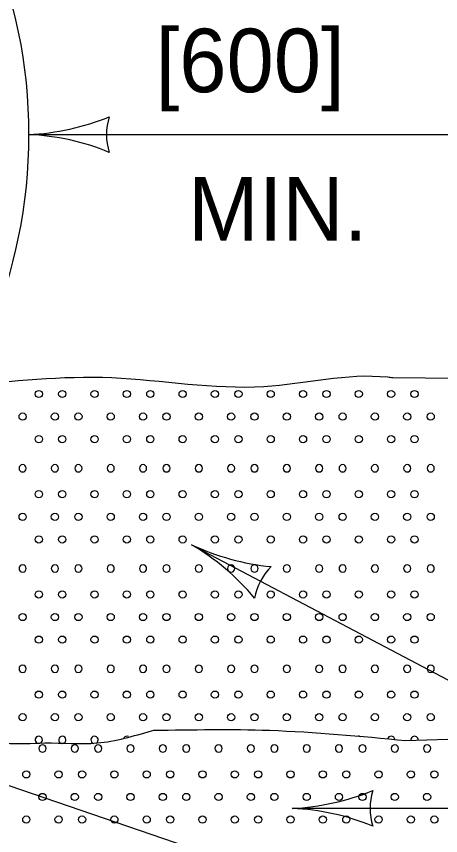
# Model space of a CAD drawing. Extents: x 49991.4 to 50021, y 49987.6 to 50011.4.
# Drawn here: x 50003.823 to 50004.224, y 49993.056 to 49993.83 of the extents above; entities that cross this region are included whole.
import ezdxf

# ---------------------------------------------------------------- set-up
doc = ezdxf.new("R2010")
doc.units = 0
for name, color, linetype in [('Level 1', 7, 'Continuous'), ('Level 2', 7, 'Continuous'), ('Level 3', 7, 'Continuous')]:
    doc.layers.add(name, color=color, linetype=linetype)

msp = doc.modelspace()

# ---------------------------------------------------------------- linework, layer by layer
at = {"layer": 'Level 1'}
msp.add_line((50003.95088, 49993.15536), (50003.95299, 49993.15586), dxfattribs=at)
for points in [[(50004.17861, 49993.48883), (50004.23958, 49993.4884), (50004.31501, 49993.48051), (50004.32066, 49993.47642)], [(50004.19101, 49993.14623), (50004.25047, 49993.14814), (50004.31739, 49993.14216)]]:
    msp.add_lwpolyline(points, dxfattribs=at)
for centre, radius in [((50003.35501, 49993.71818), 0.48), ((50003.84458, 49993.47333), 0.00341), ((50003.86672, 49993.47333), 0.00341), ((50003.8972, 49993.47333), 0.00341), ((50003.92768, 49993.47333), 0.00341), ((50003.94982, 49993.47333), 0.00341), ((50003.9803, 49993.47333), 0.00341), ((50004.01078, 49993.47333), 0.00341), ((50004.03292, 49993.47333), 0.00341), ((50004.0634, 49993.47333), 0.00341), ((50004.09388, 49993.47333), 0.00341), ((50004.11602, 49993.47333), 0.00341), ((50004.1465, 49993.47333), 0.00341), ((50004.17698, 49993.47333), 0.00341), ((50004.19912, 49993.47333), 0.00341), ((50003.82934, 49993.452), 0.00341), ((50003.82934, 49993.452), 0.00341), ((50003.85982, 49993.452), 0.00341), ((50003.88196, 49993.452), 0.00341), ((50003.91244, 49993.452), 0.00341), ((50003.91244, 49993.452), 0.00341), ((50003.94292, 49993.452), 0.00341), ((50003.96506, 49993.452), 0.00341), ((50003.99554, 49993.452), 0.00341), ((50003.99554, 49993.452), 0.00341), ((50004.02602, 49993.452), 0.00341), ((50004.04816, 49993.452), 0.00341), ((50004.07864, 49993.452), 0.00341), ((50004.07864, 49993.452), 0.00341), ((50004.10912, 49993.452), 0.00341), ((50004.13126, 49993.452), 0.00341), ((50004.16174, 49993.452), 0.00341), ((50004.16174, 49993.452), 0.00341), ((50004.19222, 49993.452), 0.00341), ((50004.21436, 49993.452), 0.00341), ((50003.84458, 49993.43066), 0.00341), ((50003.86672, 49993.43066), 0.00341), ((50003.8972, 49993.43066), 0.00341), ((50003.92768, 49993.43066), 0.00341), ((50003.94982, 49993.43066), 0.00341), ((50003.9803, 49993.43066), 0.00341), ((50004.01078, 49993.43066), 0.00341), ((50004.03292, 49993.43066), 0.00341), ((50004.0634, 49993.43066), 0.00341), ((50004.09388, 49993.43066), 0.00341), ((50004.11602, 49993.43066), 0.00341), ((50004.1465, 49993.43066), 0.00341), ((50004.17698, 49993.43066), 0.00341), ((50004.19912, 49993.43066), 0.00341), ((50003.84458, 49993.37873), 0.00341), ((50003.86672, 49993.37873), 0.00341), ((50003.8972, 49993.37873), 0.00341), ((50003.92768, 49993.37873), 0.00341), ((50003.94982, 49993.37873), 0.00341), ((50003.9803, 49993.37873), 0.00341), ((50004.01078, 49993.37873), 0.00341), ((50004.03292, 49993.37873), 0.00341), ((50004.0634, 49993.37873), 0.00341), ((50004.09388, 49993.37873), 0.00341), ((50004.11602, 49993.37873), 0.00341), ((50004.1465, 49993.37873), 0.00341), ((50004.17698, 49993.37873), 0.00341), ((50004.19912, 49993.37873), 0.00341), ((50003.82934, 49993.3574), 0.00341), ((50003.82934, 49993.3574), 0.00341), ((50003.85982, 49993.3574), 0.00341), ((50003.88196, 49993.3574), 0.00341), ((50003.91244, 49993.3574), 0.00341), ((50003.91244, 49993.3574), 0.00341), ((50003.94292, 49993.3574), 0.00341), ((50003.96506, 49993.3574), 0.00341), ((50003.99554, 49993.3574), 0.00341), ((50003.99554, 49993.3574), 0.00341), ((50004.02602, 49993.3574), 0.00341), ((50004.04816, 49993.3574), 0.00341), ((50004.07864, 49993.3574), 0.00341), ((50004.07864, 49993.3574), 0.00341), ((50004.10912, 49993.3574), 0.00341), ((50004.13126, 49993.3574), 0.00341), ((50004.16174, 49993.3574), 0.00341), ((50004.16174, 49993.3574), 0.00341), ((50004.19222, 49993.3574), 0.00341), ((50004.21436, 49993.3574), 0.00341), ((50003.84458, 49993.33606), 0.00341), ((50003.86672, 49993.33606), 0.00341), ((50003.8972, 49993.33606), 0.00341), ((50003.92768, 49993.33606), 0.00341), ((50003.94982, 49993.33606), 0.00341), ((50003.9803, 49993.33606), 0.00341), ((50004.01078, 49993.33606), 0.00341), ((50004.03292, 49993.33606), 0.00341), ((50004.0634, 49993.33606), 0.00341), ((50004.09388, 49993.33606), 0.00341), ((50004.11602, 49993.33606), 0.00341), ((50004.1465, 49993.33606), 0.00341), ((50004.17698, 49993.33606), 0.00341), ((50004.19912, 49993.33606), 0.00341), ((50003.84458, 49993.28413), 0.00341), ((50003.86672, 49993.28413), 0.00341), ((50003.8972, 49993.28413), 0.00341), ((50003.92768, 49993.28413), 0.00341), ((50003.94982, 49993.28413), 0.00341), ((50003.9803, 49993.28413), 0.00341), ((50004.01078, 49993.28413), 0.00341), ((50004.03292, 49993.28413), 0.00341), ((50004.0634, 49993.28413), 0.00341), ((50004.09388, 49993.28413), 0.00341), ((50004.11602, 49993.28413), 0.00341), ((50004.1465, 49993.28413), 0.00341), ((50004.17698, 49993.28413), 0.00341), ((50004.19912, 49993.28413), 0.00341), ((50003.82934, 49993.2628), 0.00341), ((50003.82934, 49993.2628), 0.00341), ((50003.85982, 49993.2628), 0.00341), ((50003.88196, 49993.2628), 0.00341), ((50003.91244, 49993.2628), 0.00341), ((50003.91244, 49993.2628), 0.00341), ((50003.94292, 49993.2628), 0.00341), ((50003.96506, 49993.2628), 0.00341), ((50003.99554, 49993.2628), 0.00341), ((50003.99554, 49993.2628), 0.00341), ((50004.02602, 49993.2628), 0.00341), ((50004.04816, 49993.2628), 0.00341), ((50004.07864, 49993.2628), 0.00341), ((50004.07864, 49993.2628), 0.00341), ((50004.10912, 49993.2628), 0.00341), ((50004.13126, 49993.2628), 0.00341), ((50004.16174, 49993.2628), 0.00341), ((50004.16174, 49993.2628), 0.00341), ((50004.19222, 49993.2628), 0.00341), ((50004.21436, 49993.2628), 0.00341), ((50003.84458, 49993.24146), 0.00341), ((50003.86672, 49993.24146), 0.00341), ((50003.8972, 49993.24146), 0.00341), ((50003.92768, 49993.24146), 0.00341), ((50003.94982, 49993.24146), 0.00341), ((50003.9803, 49993.24146), 0.00341), ((50004.01078, 49993.24146), 0.00341), ((50004.03292, 49993.24146), 0.00341), ((50004.0634, 49993.24146), 0.00341), ((50004.09388, 49993.24146), 0.00341), ((50004.11602, 49993.24146), 0.00341), ((50004.1465, 49993.24146), 0.00341), ((50004.17698, 49993.24146), 0.00341), ((50004.19912, 49993.24146), 0.00341), ((50003.84458, 49993.18953), 0.00341), ((50003.86672, 49993.18953), 0.00341), ((50003.8972, 49993.18953), 0.00341), ((50003.92768, 49993.18953), 0.00341), ((50003.94982, 49993.18953), 0.00341), ((50003.9803, 49993.18953), 0.00341), ((50004.01078, 49993.18953), 0.00341), ((50004.03292, 49993.18953), 0.00341), ((50004.0634, 49993.18953), 0.00341), ((50004.09388, 49993.18953), 0.00341), ((50004.11602, 49993.18953), 0.00341), ((50004.1465, 49993.18953), 0.00341), ((50004.17698, 49993.18953), 0.00341), ((50004.19912, 49993.18953), 0.00341), ((50003.82934, 49993.1682), 0.00341), ((50003.82934, 49993.1682), 0.00341), ((50003.85982, 49993.1682), 0.00341), ((50003.88196, 49993.1682), 0.00341), ((50003.91244, 49993.1682), 0.00341), ((50003.91244, 49993.1682), 0.00341), ((50003.94292, 49993.1682), 0.00341), ((50003.96506, 49993.1682), 0.00341), ((50003.99554, 49993.1682), 0.00341), ((50003.99554, 49993.1682), 0.00341), ((50004.02602, 49993.1682), 0.00341), ((50004.04816, 49993.1682), 0.00341), ((50004.07864, 49993.1682), 0.00341), ((50004.07864, 49993.1682), 0.00341), ((50004.10912, 49993.1682), 0.00341), ((50004.13126, 49993.1682), 0.00341), ((50004.16174, 49993.1682), 0.00341), ((50004.16174, 49993.1682), 0.00341), ((50004.19222, 49993.1682), 0.00341), ((50004.21436, 49993.1682), 0.00341), ((50003.8328, 49993.1143), 0.00341), ((50003.86328, 49993.1143), 0.00341), ((50003.88542, 49993.1143), 0.00341), ((50003.9159, 49993.1143), 0.00341), ((50003.94638, 49993.1143), 0.00341), ((50003.96852, 49993.1143), 0.00341), ((50003.999, 49993.1143), 0.00341), ((50004.02948, 49993.1143), 0.00341), ((50004.05162, 49993.1143), 0.00341), ((50004.0821, 49993.1143), 0.00341), ((50004.11258, 49993.1143), 0.00341), ((50004.13472, 49993.1143), 0.00341), ((50004.1652, 49993.1143), 0.00341), ((50004.19568, 49993.1143), 0.00341), ((50004.21782, 49993.1143), 0.00341), ((50003.84804, 49993.09296), 0.00341), ((50003.84804, 49993.09296), 0.00341), ((50003.87852, 49993.09296), 0.00341), ((50003.90066, 49993.09296), 0.00341), ((50003.93114, 49993.09296), 0.00341), ((50003.93114, 49993.09296), 0.00341), ((50003.96162, 49993.09296), 0.00341), ((50003.98376, 49993.09296), 0.00341), ((50004.01424, 49993.09296), 0.00341), ((50004.01424, 49993.09296), 0.00341), ((50004.04472, 49993.09296), 0.00341), ((50004.06686, 49993.09296), 0.00341), ((50004.09734, 49993.09296), 0.00341), ((50004.09734, 49993.09296), 0.00341), ((50004.12782, 49993.09296), 0.00341), ((50004.14996, 49993.09296), 0.00341), ((50004.18044, 49993.09296), 0.00341), ((50004.18044, 49993.09296), 0.00341), ((50004.21092, 49993.09296), 0.00341), ((50003.8328, 49993.07162), 0.00341), ((50003.86328, 49993.07162), 0.00341), ((50003.88542, 49993.07162), 0.00341), ((50003.9159, 49993.07162), 0.00341), ((50003.94638, 49993.07162), 0.00341), ((50003.96852, 49993.07162), 0.00341), ((50003.999, 49993.07162), 0.00341), ((50004.02948, 49993.07162), 0.00341), ((50004.05162, 49993.07162), 0.00341), ((50004.0821, 49993.07162), 0.00341), ((50004.11258, 49993.07162), 0.00341), ((50004.13472, 49993.07162), 0.00341), ((50004.1652, 49993.07162), 0.00341), ((50004.19568, 49993.07162), 0.00341), ((50004.21782, 49993.07162), 0.00341)]:
    msp.add_circle(centre, radius, dxfattribs=at)
for centre, start, end in [((50003.82934, 49993.40323), 0, 180), ((50003.85982, 49993.40323), 0, 180), ((50003.88196, 49993.40323), 0, 180), ((50003.91244, 49993.40323), 0, 180), ((50003.94292, 49993.40323), 0, 180), ((50003.96506, 49993.40323), 0, 180), ((50003.99554, 49993.40323), 0, 180), ((50004.02602, 49993.40323), 0, 180), ((50004.04816, 49993.40323), 0, 180), ((50004.07864, 49993.40323), 0, 180), ((50004.10912, 49993.40323), 0, 180), ((50004.13126, 49993.40323), 0, 180), ((50004.16174, 49993.40323), 0, 180), ((50004.19222, 49993.40323), 0, 180), ((50004.21436, 49993.40323), 0, 180), ((50003.82934, 49993.40312), 180, 0), ((50003.82934, 49993.40312), 180, 0), ((50003.85982, 49993.40312), 180, 0), ((50003.88196, 49993.40312), 180, 0), ((50003.91244, 49993.40312), 180, 0), ((50003.91244, 49993.40312), 180, 0), ((50003.94292, 49993.40312), 180, 0), ((50003.96506, 49993.40312), 180, 0), ((50003.99554, 49993.40312), 180, 0), ((50003.99554, 49993.40312), 180, 0), ((50004.02602, 49993.40312), 180, 0), ((50004.04816, 49993.40312), 180, 0), ((50004.07864, 49993.40312), 180, 0), ((50004.07864, 49993.40312), 180, 0), ((50004.10912, 49993.40312), 180, 0), ((50004.13126, 49993.40312), 180, 0), ((50004.16174, 49993.40312), 180, 0), ((50004.16174, 49993.40312), 180, 0), ((50004.19222, 49993.40312), 180, 0), ((50004.21436, 49993.40312), 180, 0), ((50003.82934, 49993.30863), 0, 180), ((50003.82934, 49993.30852), 180, 0), ((50003.82934, 49993.30852), 180, 0), ((50003.85982, 49993.30863), 0, 180), ((50003.85982, 49993.30852), 180, 0), ((50003.88196, 49993.30863), 0, 180), ((50003.88196, 49993.30852), 180, 0), ((50003.91244, 49993.30863), 0, 180), ((50003.91244, 49993.30852), 180, 0), ((50003.91244, 49993.30852), 180, 0), ((50003.94292, 49993.30863), 0, 180), ((50003.94292, 49993.30852), 180, 0), ((50003.96506, 49993.30863), 0, 180), ((50003.96506, 49993.30852), 180, 0), ((50003.99554, 49993.30863), 0, 180), ((50003.99554, 49993.30852), 180, 0), ((50003.99554, 49993.30852), 180, 0), ((50004.02602, 49993.30863), 0, 180), ((50004.02602, 49993.30852), 180, 0), ((50004.04816, 49993.30863), 0, 180), ((50004.04816, 49993.30852), 180, 0), ((50004.07864, 49993.30863), 0, 180), ((50004.07864, 49993.30852), 180, 0), ((50004.07864, 49993.30852), 180, 0), ((50004.10912, 49993.30863), 0, 180), ((50004.10912, 49993.30852), 180, 0), ((50004.13126, 49993.30863), 0, 180), ((50004.13126, 49993.30852), 180, 0), ((50004.16174, 49993.30863), 0, 180), ((50004.16174, 49993.30852), 180, 0), ((50004.16174, 49993.30852), 180, 0), ((50004.19222, 49993.30863), 0, 180), ((50004.19222, 49993.30852), 180, 0), ((50004.21436, 49993.30863), 0, 180), ((50004.21436, 49993.30852), 180, 0), ((50003.82934, 49993.21403), 0, 180), ((50003.82934, 49993.21392), 180, 0), ((50003.82934, 49993.21392), 180, 0), ((50003.85982, 49993.21403), 0, 180), ((50003.85982, 49993.21392), 180, 0), ((50003.88196, 49993.21403), 0, 180), ((50003.88196, 49993.21392), 180, 0), ((50003.91244, 49993.21403), 0, 180), ((50003.91244, 49993.21392), 180, 0), ((50003.91244, 49993.21392), 180, 0), ((50003.94292, 49993.21403), 0, 180), ((50003.94292, 49993.21392), 180, 0), ((50003.96506, 49993.21403), 0, 180), ((50003.96506, 49993.21392), 180, 0), ((50003.99554, 49993.21403), 0, 180), ((50003.99554, 49993.21392), 180, 0), ((50003.99554, 49993.21392), 180, 0), ((50004.02602, 49993.21403), 0, 180), ((50004.02602, 49993.21392), 180, 0), ((50004.04816, 49993.21403), 0, 180), ((50004.04816, 49993.21392), 180, 0), ((50004.07864, 49993.21403), 0, 180), ((50004.07864, 49993.21392), 180, 0), ((50004.07864, 49993.21392), 180, 0), ((50004.10912, 49993.21403), 0, 180), ((50004.10912, 49993.21392), 180, 0), ((50004.13126, 49993.21403), 0, 180), ((50004.13126, 49993.21392), 180, 0), ((50004.16174, 49993.21403), 0, 180), ((50004.16174, 49993.21392), 180, 0), ((50004.16174, 49993.21392), 180, 0), ((50004.19222, 49993.21403), 0, 180), ((50004.19222, 49993.21392), 180, 0), ((50004.21436, 49993.21403), 0, 180), ((50004.21436, 49993.21392), 180, 0), ((50003.84458, 49993.14686), 300.098, 239.902), ((50003.86672, 49993.14686), 279.79984, 256.08499), ((50003.8972, 49993.14686), 295.61229, 257.02348), ((50003.92768, 49993.14686), 62.7279, 145.6668), ((50004.1465, 49993.14686), 59.23674, 110.80492), ((50004.17698, 49993.14686), 3.24219, 167.34097), ((50004.19912, 49993.14686), 355.65085, 188.01415), ((50003.84804, 49993.13879), 0, 180), ((50003.87852, 49993.13879), 0, 180), ((50003.90066, 49993.13879), 0, 180), ((50003.93114, 49993.13879), 0, 180), ((50003.96162, 49993.13879), 0, 180), ((50003.98376, 49993.13879), 0, 180), ((50004.01424, 49993.13879), 0, 180), ((50004.04472, 49993.13879), 0, 180), ((50004.06686, 49993.13879), 0, 180), ((50004.09734, 49993.13879), 0, 180), ((50004.12782, 49993.13879), 0, 180), ((50004.14996, 49993.13879), 0, 180), ((50004.18044, 49993.13879), 0, 180), ((50004.21092, 49993.13879), 0, 180), ((50003.84804, 49993.13868), 180, 0), ((50003.84804, 49993.13868), 180, 0), ((50003.87852, 49993.13868), 180, 0), ((50003.90066, 49993.13868), 180, 0), ((50003.93114, 49993.13868), 180, 0), ((50003.93114, 49993.13868), 180, 0), ((50003.96162, 49993.13868), 180, 0), ((50003.98376, 49993.13868), 180, 0), ((50004.01424, 49993.13868), 180, 0), ((50004.01424, 49993.13868), 180, 0), ((50004.04472, 49993.13868), 180, 0), ((50004.06686, 49993.13868), 180, 0), ((50004.09734, 49993.13868), 180, 0), ((50004.09734, 49993.13868), 180, 0), ((50004.12782, 49993.13868), 180, 0), ((50004.14996, 49993.13868), 180, 0), ((50004.18044, 49993.13868), 180, 0), ((50004.18044, 49993.13868), 180, 0), ((50004.21092, 49993.13868), 180, 0)]:
    msp.add_arc(centre, 0.00341, start, end, dxfattribs=at)
for points in [[(50003.77213, 49993.48068), (50003.91338, 49993.48878), (50004.057, 49993.48051), (50004.17384, 49993.48939), (50004.17861, 49993.48883)], [(50003.59505, 49993.14423), (50003.66331, 49993.14423), (50003.73964, 49993.16038), (50003.81299, 49993.14391), (50003.85041, 49993.14391), (50003.8998, 49993.14391), (50003.95088, 49993.15536)], [(50003.95299, 49993.15586), (50004.06229, 49993.15586), (50004.19101, 49993.14623)]]:
    msp.add_spline(points, degree=3, dxfattribs=at)
at = {"layer": 'Level 3'}
for p, q in [((50003.83501, 49993.71818), (50004.31501, 49993.71818)), ((50003.98875, 49993.33099), (50004.4608, 49993.08212)), ((50004.45887, 49992.88403), (50003.50267, 49993.21045)), ((50004.45902, 49993.08212), (50004.08366, 49993.08212))]:
    msp.add_line(p, q, dxfattribs=at)
for centre, radius, start, end in [((50003.82351, 49993.9509), 0.233, 272.82731, 292.07716), ((50003.96322, 49993.71818), 0.05477, 162.13882, 197.86118), ((50003.82585, 49993.49605), 0.22232, 67.45601, 87.63952), ((50003.87705, 49993.13876), 0.22232, 39.65749, 59.841), ((50004.08711, 49993.54221), 0.233, 245.02879, 264.27864), ((50004.10217, 49993.2712), 0.05477, 134.3403, 170.06266), ((50004.07216, 49993.31483), 0.233, 272.82731, 292.07716), ((50004.21187, 49993.08212), 0.05477, 162.13882, 197.86118), ((50004.0745, 49992.85999), 0.22232, 67.45601, 87.63952)]:
    msp.add_arc(centre, radius, start, end, dxfattribs=at)

# ---------------------------------------------------------------- texts
at = {"layer": 'Level 2'}
for s, p in [('[600]', (50003.95479, 49993.75818)), ('MIN.', (50003.98526, 49993.61818))]:
    msp.add_text(s, height=0.06, dxfattribs=at).set_placement(p)

doc.saveas('drawing.dxf')
